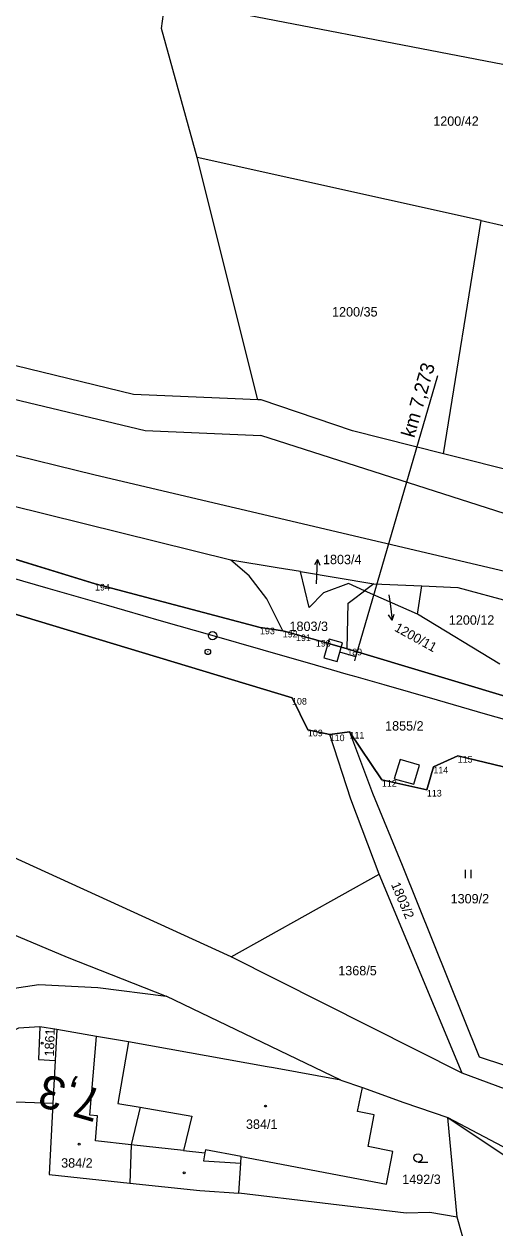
# Model space of a CAD drawing. Extents: x -779330 to -774454, y -1144748 to -1142831.
# Drawn here: x -777413.3 to -777328.3, y -1143849.7 to -1143632.3 of the extents above; entities that cross this region are included whole.
import ezdxf

# ---------------------------------------------------------------- set-up
doc = ezdxf.new("R2010")
doc.units = 0
for name, color, linetype in [('Hranice parcel', 7, 'Continuous'), ('Parcelní čísla', 7, 'Continuous'), ('Pop  PČ popisy', 7, 'Continuous'), ('SŽDC', 7, 'Continuous'), ('Vnitřní kresba', 7, 'Continuous'), ('Vrstva 1', 7, 'Continuous'), ('Vrstva 53', 7, 'Continuous'), ('Vrstva 60', 7, 'Continuous'), ('Vrstva 7', 7, 'Continuous'), ('Značky budov', 7, 'Continuous'), ('Značky kultur', 7, 'Continuous')]:
    doc.layers.add(name, color=color, linetype=linetype)

msp = doc.modelspace()

# ---------------------------------------------------------------- linework, layer by layer
at = {"layer": 'Hranice parcel'}
for p, q in [((-777387.79, -1143627.73), (-777289.42, -1143646.86)), ((-777330.78, -1143667.78), (-777382.09, -1143656.4)), ((-777371.14, -1143700.16), (-777382.09, -1143656.4)), ((-777337.58, -1143709.93), (-777330.78, -1143667.78)), ((-777330.78, -1143667.78), (-777312.14, -1143672.14)), ((-777320.68, -1143714.19), (-777337.58, -1143709.93)), ((-777442.54, -1143720.48), (-777400.53, -1143733.41)), ((-777363.43, -1143731.19), (-777350.2, -1143733.4)), ((-777350.2, -1143733.4), (-777351.84, -1143734.64)), ((-777350.2, -1143733.4), (-777341.48, -1143733.78)), ((-777342.31, -1143738.85), (-777341.48, -1143733.78)), ((-777342.31, -1143738.85), (-777351.84, -1143734.64)), ((-777327.45, -1143747.9), (-777342.31, -1143738.85)), ((-777354.56, -1143760.13), (-777358.14, -1143760.61)), ((-777375.94, -1143800.75), (-777349.24, -1143785.82)), ((-777334.23, -1143821.79), (-777349.24, -1143785.82)), ((-777334.23, -1143821.79), (-777375.94, -1143800.75)), ((-777356.13, -1143823.03), (-777387.68, -1143807.89)), ((-777407.46, -1143813.89), (-777410.51, -1143813.42)), ((-777407.46, -1143813.89), (-777407.75, -1143819.47)), ((-777407.75, -1143819.47), (-777408.15, -1143827.26)), ((-777356.13, -1143823.03), (-777352.24, -1143824.36)), ((-777326.59, -1143824.61), (-777334.23, -1143821.79)), ((-777408.15, -1143827.26), (-777418.55, -1143826.88)), ((-777336.84, -1143829.8), (-777325.74, -1143837.19)), ((-777335.13, -1143847.76), (-777336.84, -1143829.8)), ((-777327.16, -1143876.09), (-777335.13, -1143847.76))]:
    msp.add_line(p, q, dxfattribs=at)
for points in [[(-777375.98, -1143729.1), (-777462.56, -1143707.72), (-777543.96, -1143687.61), (-777544.8, -1143687.4), (-777564.35, -1143682.38), (-777643.12, -1143662.79), (-777672.41, -1143655.46), (-777784.28, -1143627.47), (-777786.92, -1143627.45)], [(-777382.09, -1143656.4), (-777388.54, -1143633.14), (-777387.79, -1143627.73)], [(-777371.14, -1143700.16), (-777375.2, -1143699.98), (-777393.58, -1143699.19), (-777466.8, -1143681.38), (-777472.61, -1143679.64), (-777508.79, -1143668.8)], [(-777358.14, -1143760.61), (-777362.08, -1143759.74), (-777364.95, -1143754.01), (-777547.63, -1143698.79)], [(-777337.58, -1143709.93), (-777354.06, -1143705.78), (-777370.54, -1143700.19), (-777371.14, -1143700.16)], [(-777375.94, -1143800.75), (-777415.86, -1143782.49), (-777462.27, -1143762.62), (-777556.08, -1143726.43)], [(-777363.43, -1143731.19), (-777367.61, -1143730.49), (-777375.98, -1143729.1)], [(-777366.62, -1143741.88), (-777369.53, -1143736.13), (-777372.68, -1143731.94), (-777375.98, -1143729.1)], [(-777351.84, -1143734.64), (-777354.77, -1143733.35), (-777359.28, -1143735.02), (-777361.87, -1143737.69), (-777363.43, -1143731.19)], [(-777400.53, -1143733.41), (-777370.73, -1143741.3), (-777366.62, -1143741.88)], [(-777341.48, -1143733.78), (-777335, -1143734.07), (-777325.2, -1143736.7)], [(-777354.97, -1143745.11), (-777354.79, -1143736.89), (-777354.11, -1143736.37), (-777351.84, -1143734.64)], [(-777366.62, -1143741.88), (-777364.22, -1143742.54), (-777360.64, -1143743.54), (-777354.97, -1143745.11)], [(-776969.85, -1143863.66), (-776987.47, -1143857.88), (-777014.89, -1143846.57), (-777042.6, -1143836.95), (-777069.03, -1143828.43), (-777082.24, -1143824.08), (-777130.76, -1143810.13), (-777274.26, -1143769.36), (-777322.71, -1143754.8), (-777354.97, -1143745.11)], [(-777321.99, -1143767.59), (-777335.02, -1143764.48), (-777339.43, -1143766.44), (-777340.59, -1143770.61), (-777348.72, -1143768.82), (-777354.56, -1143760.13)], [(-777354.56, -1143760.13), (-777350.41, -1143771.21), (-777345.05, -1143784.18), (-777331.15, -1143818.8), (-777326.6, -1143820.32)], [(-777349.24, -1143785.82), (-777354.31, -1143772.3), (-777358.14, -1143760.61)], [(-777437.2, -1143787.51), (-777405.54, -1143800.83), (-777387.68, -1143807.89)], [(-777465.49, -1143832.81), (-777457.92, -1143830.94), (-777435.72, -1143811.54), (-777423.12, -1143807.62), (-777410.71, -1143805.75), (-777400, -1143806.27), (-777387.68, -1143807.89)], [(-777410.51, -1143813.42), (-777414.33, -1143813.66), (-777426.36, -1143819.29), (-777430, -1143821.16)], [(-777410.51, -1143813.42), (-777410.76, -1143819.32), (-777407.75, -1143819.47)], [(-777394.47, -1143816.13), (-777400.29, -1143815.13), (-777407.46, -1143813.89)], [(-777394.47, -1143816.13), (-777396.39, -1143827.22), (-777392.36, -1143827.92), (-777394, -1143834.68), (-777394.22, -1143841.61)], [(-777356.13, -1143823.03), (-777368.31, -1143820.81), (-777369.47, -1143820.6), (-777394.47, -1143816.13)], [(-777374.57, -1143843.43), (-777374.21, -1143838.03), (-777374.13, -1143836.83), (-777347.87, -1143841.8), (-777346.72, -1143835.94), (-777351.23, -1143835), (-777350.1, -1143829.26), (-777353.11, -1143828.68), (-777352.24, -1143824.36)], [(-777352.24, -1143824.36), (-777344.73, -1143827.04), (-777336.84, -1143829.8)], [(-777408.15, -1143827.26), (-777408.81, -1143840.04), (-777394.22, -1143841.61)], [(-777336.84, -1143829.8), (-777324.83, -1143836.1), (-777303.85, -1143844.86), (-777303.16, -1143845.03)], [(-777394.22, -1143841.61), (-777381.61, -1143842.97), (-777374.57, -1143843.43)], [(-777335.13, -1143847.76), (-777340.09, -1143846.92), (-777344.36, -1143847.04), (-777374.57, -1143843.43)]]:
    msp.add_lwpolyline(points, dxfattribs=at)
at = {"layer": 'Pop  PČ popisy'}
for p, q in [((-777360.38, -1143729), (-777360.91, -1143729.98)), ((-777360.48, -1143732), (-777360.38, -1143729)), ((-777360.38, -1143729), (-777359.91, -1143730.02)), ((-777360.54, -1143733.39), (-777360.48, -1143732)), ((-777347.46, -1143735.37), (-777347.25, -1143736.96)), ((-777347.25, -1143736.96), (-777346.88, -1143739.94)), ((-777346.88, -1143739.94), (-777347.5, -1143739.01)), ((-777346.88, -1143739.94), (-777346.51, -1143738.88))]:
    msp.add_line(p, q, dxfattribs=at)
at = {"layer": 'SŽDC'}
for points in [[(-777130.76, -1143810.13), (-777274.26, -1143769.36), (-777322.71, -1143754.8), (-777354.97, -1143745.11), (-777360.64, -1143743.54), (-777364.22, -1143742.54), (-777366.62, -1143741.88), (-777370.73, -1143741.3), (-777400.53, -1143733.41), (-777442.54, -1143720.48), (-777447.49, -1143719.07), (-777546.18, -1143690.99), (-777600.4, -1143675.56), (-777619.92, -1143670.03)], [(-777622.38, -1143677.44), (-777550.6, -1143697.9), (-777547.63, -1143698.79), (-777364.95, -1143754.01), (-777362.08, -1143759.74), (-777358.14, -1143760.61), (-777354.56, -1143760.13), (-777348.72, -1143768.82), (-777340.59, -1143770.61)], [(-777340.59, -1143770.61), (-777339.43, -1143766.44), (-777335.02, -1143764.48), (-777321.99, -1143767.59), (-777306.65, -1143771.6), (-777305.36, -1143768.26), (-777304.91, -1143767.08), (-777286.34, -1143773.47), (-777251.91, -1143783.05), (-777251.55, -1143783.03), (-777238.03, -1143787.25), (-777223.03, -1143791.52), (-777208.67, -1143795.71), (-777200.02, -1143798.42), (-777184.53, -1143802.76), (-777180.06, -1143803.98), (-777171.85, -1143806.53), (-777132.17, -1143818.13)]]:
    msp.add_lwpolyline(points, dxfattribs=at)
at = {"layer": 'Vnitřní kresba'}
for p, q in [((-777509.28, -1143677.62), (-777391.49, -1143705.71)), ((-777511.09, -1143686.61), (-777400.48, -1143713.69)), ((-777391.49, -1143705.71), (-777370.58, -1143706.63)), ((-777312.68, -1143725.18), (-777370.58, -1143706.63)), ((-777400.48, -1143713.69), (-777316.11, -1143733.54)), ((-777345.45, -1143765.14), (-777346.48, -1143768.64)), ((-777341.95, -1143766.12), (-777345.45, -1143765.14)), ((-777342.94, -1143769.58), (-777341.95, -1143766.12)), ((-777346.48, -1143768.64), (-777342.94, -1143769.58)), ((-777401.46, -1143829.38), (-777400.29, -1143815.13)), ((-777400.06, -1143829.5), (-777401.46, -1143829.38)), ((-777400.42, -1143833.97), (-777400.06, -1143829.5)), ((-777392.36, -1143827.92), (-777383.05, -1143829.53)), ((-777383.05, -1143829.53), (-777384.55, -1143835.72)), ((-777394, -1143834.68), (-777400.42, -1143833.97)), ((-777384.55, -1143835.72), (-777394, -1143834.68)), ((-777384.55, -1143835.72), (-777380.68, -1143836.15)), ((-777380.68, -1143836.15), (-777380.95, -1143837.57)), ((-777380.58, -1143835.61), (-777380.68, -1143836.15)), ((-777374.13, -1143836.83), (-777380.58, -1143835.61)), ((-777380.95, -1143837.57), (-777374.21, -1143838.03))]:
    msp.add_line(p, q, dxfattribs=at)
at = {"layer": 'Vrstva 1'}
msp.add_lwpolyline([(-777319.98, -1143759.79), (-777330, -1143756.91), (-777338.69, -1143754.41), (-777348.32, -1143751.65), (-777353.34, -1143750.21), (-777355.15, -1143749.69), (-777357.83, -1143748.92), (-777360.74, -1143748.09), (-777370.17, -1143745.38), (-777379.39, -1143742.73), (-777388.51, -1143740.12), (-777398.46, -1143737.26), (-777408.97, -1143734.24), (-777420.06, -1143731.06)], dxfattribs=at)
at = {"layer": 'Vrstva 53'}
for points in [[(-777619.92, -1143670.03), (-777600.4, -1143675.56), (-777546.18, -1143690.99), (-777447.49, -1143719.07), (-777442.54, -1143720.48), (-777400.53, -1143733.41), (-777370.73, -1143741.3), (-777366.62, -1143741.88), (-777364.22, -1143742.54), (-777360.64, -1143743.54), (-777354.97, -1143745.11), (-777322.71, -1143754.8), (-777274.26, -1143769.36), (-777130.76, -1143810.13)], [(-777619.92, -1143670.03), (-777600.4, -1143675.56), (-777546.18, -1143690.99), (-777447.49, -1143719.07), (-777442.54, -1143720.48), (-777400.53, -1143733.41), (-777370.73, -1143741.3), (-777366.62, -1143741.88), (-777364.22, -1143742.54), (-777360.64, -1143743.54), (-777354.97, -1143745.11), (-777322.71, -1143754.8), (-777274.26, -1143769.36), (-777130.76, -1143810.13)], [(-777340.59, -1143770.61), (-777348.72, -1143768.82), (-777354.56, -1143760.13), (-777358.14, -1143760.61), (-777362.08, -1143759.74), (-777364.95, -1143754.01), (-777547.63, -1143698.79), (-777550.6, -1143697.9), (-777622.38, -1143677.44)], [(-777340.59, -1143770.61), (-777348.72, -1143768.82), (-777354.56, -1143760.13), (-777358.14, -1143760.61), (-777362.08, -1143759.74), (-777364.95, -1143754.01), (-777547.63, -1143698.79), (-777550.6, -1143697.9), (-777622.38, -1143677.44)], [(-777132.17, -1143818.13), (-777171.85, -1143806.53), (-777180.06, -1143803.98), (-777184.53, -1143802.76), (-777200.02, -1143798.42), (-777208.67, -1143795.71), (-777223.03, -1143791.52), (-777238.03, -1143787.25), (-777251.55, -1143783.03), (-777251.91, -1143783.05), (-777286.34, -1143773.47), (-777304.91, -1143767.08), (-777305.36, -1143768.26), (-777306.65, -1143771.6), (-777321.99, -1143767.59), (-777335.02, -1143764.48), (-777339.43, -1143766.44), (-777340.59, -1143770.61)], [(-777132.17, -1143818.13), (-777171.85, -1143806.53), (-777180.06, -1143803.98), (-777184.53, -1143802.76), (-777200.02, -1143798.42), (-777208.67, -1143795.71), (-777223.03, -1143791.52), (-777238.03, -1143787.25), (-777251.55, -1143783.03), (-777251.91, -1143783.05), (-777286.34, -1143773.47), (-777304.91, -1143767.08), (-777305.36, -1143768.26), (-777306.65, -1143771.6), (-777321.99, -1143767.59), (-777335.02, -1143764.48), (-777339.43, -1143766.44), (-777340.59, -1143770.61)]]:
    msp.add_lwpolyline(points, dxfattribs=at)
at = {"layer": 'Vrstva 60'}
for p, q in [((-777400.53, -1143733.41), (-777400.53, -1143733.41)), ((-777370.73, -1143741.3), (-777370.73, -1143741.3)), ((-777366.62, -1143741.88), (-777366.62, -1143741.88)), ((-777364.22, -1143742.54), (-777364.22, -1143742.54)), ((-777360.64, -1143743.54), (-777360.64, -1143743.54)), ((-777354.97, -1143745.11), (-777354.97, -1143745.11)), ((-777364.95, -1143754.01), (-777364.95, -1143754.01)), ((-777362.08, -1143759.74), (-777362.08, -1143759.74)), ((-777354.56, -1143760.13), (-777354.56, -1143760.13)), ((-777358.14, -1143760.61), (-777358.14, -1143760.61)), ((-777335.02, -1143764.48), (-777335.02, -1143764.48)), ((-777339.43, -1143766.44), (-777339.43, -1143766.44)), ((-777348.72, -1143768.82), (-777348.72, -1143768.82)), ((-777340.59, -1143770.61), (-777340.59, -1143770.61))]:
    msp.add_line(p, q, dxfattribs=at)
at = {"layer": 'Vrstva 7'}
for p, q in [((-777353.43, -1143746.58), (-777338.6, -1143695.77)), ((-777380.1, -1143745.7), (-777380.19, -1143745.68)), ((-777353.63, -1143747.3), (-777353.22, -1143745.86))]:
    msp.add_line(p, q, dxfattribs=at)
msp.add_lwpolyline([(-777353.43, -1143746.58), (-777356.31, -1143745.75), (-777355.83, -1143744.07), (-777358.23, -1143743.38), (-777359.2, -1143746.75), (-777356.79, -1143747.43), (-777356.31, -1143745.75)], dxfattribs=at)
for centre, radius in [((-777379.31, -1143742.76), 0.75), ((-777380.15, -1143745.69), 0.5)]:
    msp.add_circle(centre, radius, dxfattribs=at)
at = {"layer": 'Značky budov'}
for centre in [(-777410.1, -1143816.34), (-777369.73, -1143827.7), (-777403.39, -1143834.61), (-777384.44, -1143839.75)]:
    msp.add_circle(centre, 0.175, dxfattribs=at)
at = {"layer": 'Značky kultur'}
for p, q in [((-777333.62, -1143786.55), (-777333.62, -1143785.05)), ((-777332.62, -1143786.55), (-777332.62, -1143785.05)), ((-777342.2, -1143837.81), (-777340.45, -1143837.81))]:
    msp.add_line(p, q, dxfattribs=at)
msp.add_circle((-777342.2, -1143837.06), 0.75, dxfattribs=at)

# ---------------------------------------------------------------- texts
at = {"layer": 'Parcelní čísla'}
for s, p in [('1200/42', (-777339.45, -1143650.69)), ('1200/35', (-777357.72, -1143685.13)), ('1803/4', (-777359.36, -1143729.85)), ('1803/3', (-777365.41, -1143741.92)), ('1200/12', (-777336.63, -1143740.78)), ('1855/2', (-777348.14, -1143759.9)), ('1309/2', (-777336.31, -1143791.11)), ('1368/5', (-777356.6, -1143804.1)), ('384/1', (-777373.27, -1143831.83)), ('384/2', (-777406.65, -1143838.83)), ('1492/3', (-777345.05, -1143841.78))]:
    msp.add_text(s, height=1.7, dxfattribs=at).set_placement(p)
for s, rotation, p in [('1200/11', 331, (-777346.6, -1143741.81)), ('1803/2', 293, (-777347.11, -1143787.69)), ('1861', 88, (-777407.97, -1143818.78))]:
    msp.add_text(s, height=1.7, rotation=rotation, dxfattribs=at).set_placement(p)
at = {"layer": 'Vrstva 60'}
for s, p in [('194', (-777400.53, -1143734.61)), ('193', (-777370.73, -1143742.5)), ('192', (-777366.62, -1143743.08)), ('191', (-777364.22, -1143743.74)), ('190', (-777360.64, -1143744.74)), ('189', (-777354.97, -1143746.31)), ('108', (-777364.95, -1143755.21)), ('109', (-777362.08, -1143760.94)), ('111', (-777354.56, -1143761.33)), ('110', (-777358.14, -1143761.81)), ('115', (-777335.02, -1143765.68)), ('114', (-777339.43, -1143767.64)), ('112', (-777348.72, -1143770.02)), ('113', (-777340.59, -1143771.81))]:
    msp.add_text(s, height=1.2, dxfattribs=at).set_placement(p)
at = {"layer": 'Vrstva 7'}
for s, height, rotation, p in [('km 7,273', 2.5, 73.9938, (-777342.89, -1143707.15)), ('7,3', 6, 163.9805, (-777398.9, -1143824.91))]:
    msp.add_text(s, height=height, rotation=rotation, dxfattribs=at).set_placement(p)

doc.saveas('drawing.dxf')
